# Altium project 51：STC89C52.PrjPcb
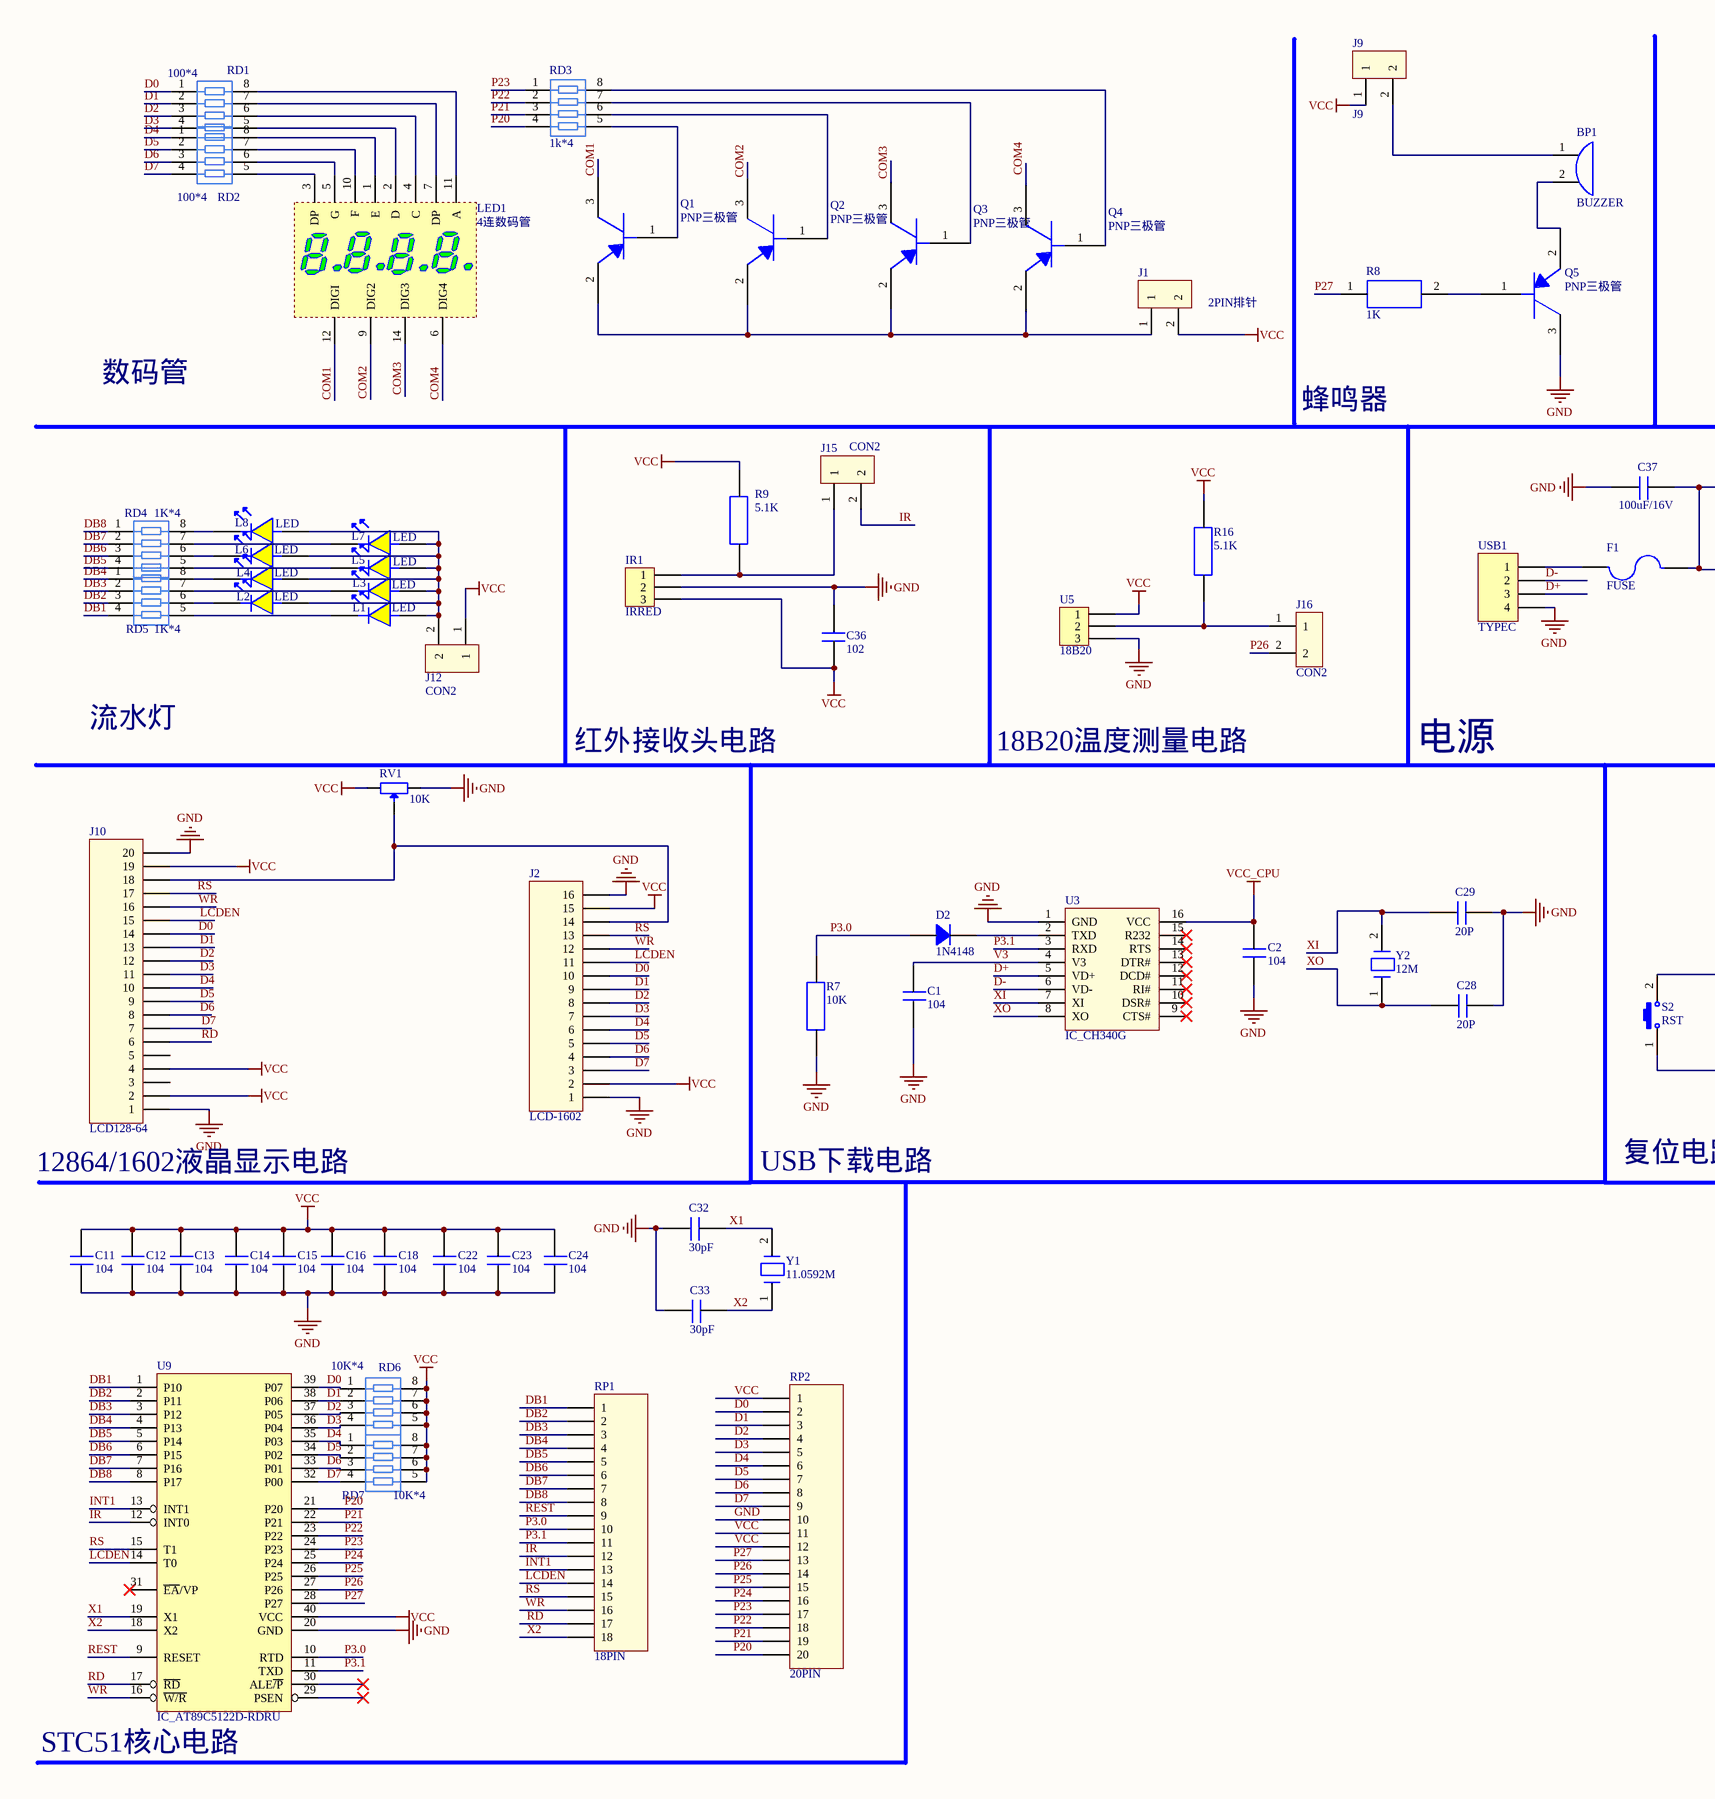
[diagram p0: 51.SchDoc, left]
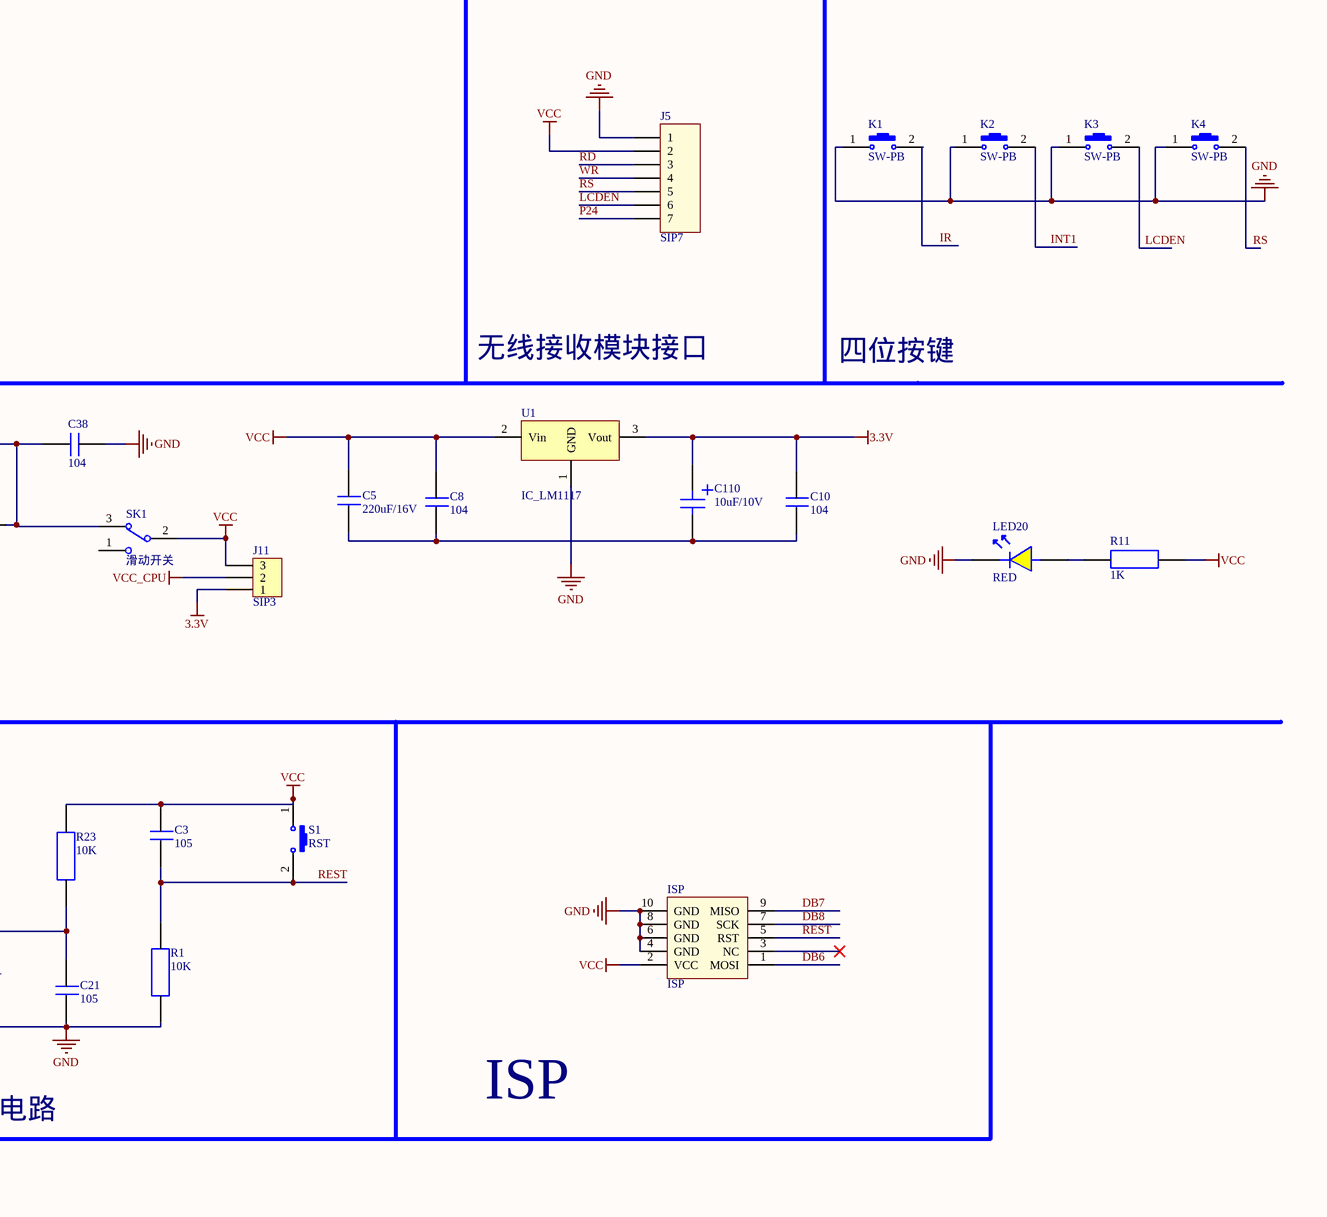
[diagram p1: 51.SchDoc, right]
1 sheet, 85 parts. Net scope: global (net labels, ports and power ports of the same name join across sheets).
Board file: 51.PcbDoc

## Sheet 51.SchDoc
size A2; SheetNumber: 1; SheetTotal: 1

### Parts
BP1  BUZZER  [BUZZER]
C1  104  [FPC-0402C]
C2  104  [FPC-0402C]
C3  105  [FPC-0402C]
C5  220uF/16V  [FPC-0402C]
C8  104  [FPC-0402C]
C10  104  [FPC-0402C]
C11  104  [FPC-0402C]
C12  104  [FPC-0402C]
C13  104  [FPC-0402C]
C14  104  [FPC-0402C]
C15  104  [FPC-0402C]
C16  104  [FPC-0402C]
C18  104  [FPC-0402C]
C21  105  [FPC-0402C]
C22  104  [FPC-0402C]
C23  104  [FPC-0402C]
C24  104  [FPC-0402C]
C28  20P  [FPC-0402C]
C29  20P  [FPC-0402C]
C32  30pF  [FPC-0402C]
C33  30pF  [FPC-0402C]
C36  102  [FPC-0402C]
C37  100uF/16V  [FPC-CPCSM-3R2X8R0-1]
C38  104  [FPC-0402C]
C110  10uF/10V  [FPC-0402C]
D2  1N4148  [FPC-1206D]
F1  FUSE  [1206F]
IR1  IRRED  [HDR1X3]
ISP  ISP  [IDE-10]
J1  2PIN排针  [HDR1X2]
J2  LCD-1602  [HDR1X16]
J5  SIP7  [HDR1X7]
J9  J9  [HDR1X2]
J10  LCD128-64  [HDR1X20]
J11  SIP3  [HDR1X3]
J12  CON2  [HDR1X2]
J15  CON2  [HDR1X2]
J16  CON2  [HDR1X2]
K1  SW-PB  [SW-PB]
K2  SW-PB  [SW-PB]
K3  SW-PB  [SW-PB]
K4  SW-PB  [SW-PB]
L1  LED  [FPC-0805D]
L2  LED  [FPC-0805D]
L3  LED  [FPC-0805D]
L4  LED  [FPC-0805D]
L5  LED  [FPC-0805D]
L6  LED  [FPC-0805D]
L7  LED  [FPC-0805D]
L8  LED  [FPC-0805D]
LED1  4连数码管  [CL3641A]
LED20  RED  [FPC-0805D]
Q1  PNP三极管  [FPC-SOT323]
Q2  PNP三极管  [FPC-SOT323]
Q3  PNP三极管  [FPC-SOT323]
Q4  PNP三极管  [FPC-SOT323]
Q5  PNP三极管  [FPC-SOT323]
R1  10K  [FPC-0402R]
R7  10K  [FPC-0402R]
R8  1K  [FPC-0402R]
R9  5.1K  [FPC-0402R]
R11  1K  [FPC-0402R]
R16  5.1K  [FPC-0402R]
R23  10K  [FPC-0402R]
RD1  100*4  [FPC-0603RA]
RD2  100*4  [FPC-0603RA]
RD3  1k*4  [FPC-0603RA]
RD4  1K*4  [FPC-0603RA]
RD5  1K*4  [FPC-0603RA]
RD6  10K*4  [FPC-0603RA]
RD7  10K*4  [FPC-0603RA]
RP1  18PIN  [HDR1X18]
RP2  20PIN  [HDR1X20]
RV1  10K  [RV]
S1  RST  [SW-PB]
S2  RST  [SW-PB]
SK1  滑动开关  [SS-12F44]
U1  IC_LM1117  [SOP-223-3L]
U3  IC_CH340G  [FPC-SO16-150]
U5  18B20  [HDR1X3]
U9  IC_AT89C5122D-RDRU  [DIP40]
USB1  TYPEC  [USB_A]
Y1  11.0592M  [FPC-CO2-5R0X11R5-V]
Y2  12M  [FPC-CO2-5R0X11R5-V]

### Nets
3.3V: C10.2 C110.1 J11.1 U1.3(Vout)
GND: C1.1 C2.1 C11.1 C12.1 C13.1 C14.1 C15.1 C16.1 C18.1 C21.1 C22.1 C23.1 C24.1 C28.2 C29.2 C32.1 C33.1 C36.1 C37.1 C38.2 IR1.2 ISP.4(GND) ISP.6(GND) ISP.8(GND) ISP.10(GND) J2.1 J2.16 J5.1 J10.1 J10.20 K1.1 K2.1 K3.1 K4.1 LED20.1 Q5.3 R1.1 R7.1 RP2.10 RV1.2 S2.1 U1.1(GND) U3.1(GND) U5.3 U9.20(GND) USB1.4
VCC: C3.2 C5.2 C8.2 C11.2 C12.2 C13.2 C14.2 C15.2 C16.2 C18.2 C22.2 C23.2 C24.2 C36.2 IR1.3 ISP.2(VCC) J1.2 J2.2 J2.15 J5.2 J9.1 J10.2 J10.4 J10.19 J11.3 J12.1 R9.2 R11.2 R16.2 R23.2 RD6.5 RD6.6 RD6.7 RD6.8 RD7.5 RD7.6 RD7.7 RD7.8 RP2.1 RP2.11 RP2.12 RV1.1 S1.1 SK1.2 U1.2(Vin) U5.1 U9.40(VCC)
VCC_CPU: C2.2 J11.2 U3.16(VCC)
COM1: LED1.12(DIGI) Q1.3
COM2: LED1.9(DIG2) Q2.3
COM3: LED1.14(DIG3) Q3.3
COM4: LED1.6(DIG4) Q4.3
D0: J2.10 J10.14 RD1.1 RD6.1 RP2.2 U9.39(P07)
D1: J2.9 J10.13 RD1.2 RD6.2 RP2.3 U9.38(P06)
D2: J2.8 J10.12 RD1.3 RD6.3 RP2.4 U9.37(P05)
D3: J2.7 J10.11 RD1.4 RD6.4 RP2.5 U9.36(P04)
D4: J2.6 J10.10 RD2.1 RD7.1 RP2.6 U9.35(P03)
D5: J2.5 J10.9 RD2.2 RD7.2 RP2.7 U9.34(P02)
D6: J2.4 J10.8 RD2.3 RD7.3 RP2.8 U9.33(P01)
D7: J2.3 J10.7 RD2.4 RD7.4 RP2.9 U9.32(P00)
D+: U3.5(VD+) USB1.3
D-: U3.6(VD-) USB1.2
DB1: RD5.4 RP1.1 U9.1(P10)
DB2: RD5.3 RP1.2 U9.2(P11)
DB3: RD5.2 RP1.3 U9.3(P12)
DB4: RD5.1 RP1.4 U9.4(P13)
DB5: RD4.4 RP1.5 U9.5(P14)
DB6: ISP.1(MOSI) RD4.3 RP1.6 U9.6(P15)
DB7: ISP.9(MISO) RD4.2 RP1.7 U9.7(P16)
DB8: ISP.7(SCK) RD4.1 RP1.8 U9.8(P17)
INT1: K2.2 RP1.13 U9.13(INT1)
IR: J15.2 K1.2 RP1.12 U9.12(INT0)
LCDEN: J2.11 J5.6 J10.15 K3.2 RP1.14 U9.14(T0)
P3.0: D2.1 R7.2 RP1.10 U9.10(RTD)
P3.1: RP1.11 U3.3(RXD) U9.11(TXD)
P20: RD3.4 RP2.20 U9.21(P20)
P21: RD3.3 RP2.19 U9.22(P21)
P22: RD3.2 RP2.18 U9.23(P22)
P23: RD3.1 RP2.17 U9.24(P23)
P24: J5.7 RP2.16 U9.25(P24)
P25: RP2.15 U9.26(P25)
P26: J16.2 RP2.14 U9.27(P26)
P27: R8.1 RP2.13 U9.28(P27)
RD: J5.3 J10.6 RP1.17 U9.17(~{RD})
REST: C3.1 ISP.5(RST) R1.2 RP1.9 S1.2 U9.9(RESET)
RS: J2.13 J5.5 J10.17 K4.2 RP1.15 U9.15(T1)
V3: C1.2 U3.4(V3)
WR: J2.12 J5.4 J10.16 RP1.16 U9.16(~{W}~{/R})
X1: C32.2 U9.19(X1) Y1.2
X2: C33.2 RP1.18 U9.18(X2) Y1.1
XI: C29.1 U3.7(XI) Y2.2
XO: C28.1 U3.8(XO) Y2.1
NetBP1_1: BP1.1 J9.2
NetBP1_2: BP1.2 Q5.2
NetC5_1: C5.1 C8.1 C10.1 C110.2
NetC21_2: C21.2 R23.1 S2.2
NetC37_2: C37.2 C38.1 F1.1 SK1.3
NetD2_2: D2.2 U3.2(TXD)
NetF1_2: F1.2 USB1.1
NetIR1_1: IR1.1 J15.1 R9.1
NetJ1_1: J1.1 Q1.2 Q2.2 Q3.2 Q4.2
NetJ2_14: J2.14 J10.18 RV1.3
NetJ12_2: J12.2 L1.2 L2.2 L3.2 L4.2 L5.2 L6.2 L7.2 L8.2
NetJ16_1: J16.1 R16.1 U5.2
NetL1_1: L1.1 RD5.5
NetL2_1: L2.1 RD5.6
NetL3_1: L3.1 RD5.7
NetL4_1: L4.1 RD5.8
NetL5_1: L5.1 RD4.5
NetL6_1: L6.1 RD4.6
NetL7_1: L7.1 RD4.7
NetL8_1: L8.1 RD4.8
NetLED1_1: LED1.1(E) RD2.8
NetLED1_2: LED1.2(D) RD1.5
NetLED1_3: LED1.3(DP) RD2.5
NetLED1_4: LED1.4(C) RD1.6
NetLED1_5: LED1.5(G) RD2.6
NetLED1_7: LED1.7(DP) RD1.7
NetLED1_10: LED1.10(F) RD2.7
NetLED1_11: LED1.11(A) RD1.8
NetLED20_2: LED20.2 R11.1
NetQ1_1: Q1.1 RD3.5
NetQ2_1: Q2.1 RD3.6
NetQ3_1: Q3.1 RD3.7
NetQ4_1: Q4.1 RD3.8
NetQ5_1: Q5.1 R8.2

Not connected (* = marked no-connect by the designer): ISP 3(NC)*; J10 3 5; SK1 1; U3 9(CTS#)* 10(DSR#)* 11(RI#)* 12(DCD#)* 13(DTR#)* 14(RTS)* 15(R232)*; U9 29(PSEN)* 30(ALE~{/P})* 31(~{EA}/VP)*

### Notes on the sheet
- 数码管
- 蜂鸣器
- 无线接收模块接口
- 四位按键
- 流水灯
- 红外接收头电路
- 18B20温度测量电路
- 电源
- (near J10) 12864/1602液晶显示电路
- USB下载电路
- 复位电路
- ISP
- (near U9) STC51核心电路

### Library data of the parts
C1-C3 C5 C8 C10-C16 C18 C21-C24 C28 C29 C32 C33 C36-C38 = CAP
C110 = CAP1
D2 = 二极管
IR1 U5 = SIP3
ISP = IC_ISP
J2 = 16PIN
J9 J12 J15 J16 = 2PIN排针
J10 = 20PIN
K1-K4 S1 S2 = KEY
LED20 = LED
R1 R7-R9 R11 R16 R23 = res1
RD1-RD7 = RP
RV1 = VR
USB1 = USB座
Y1 Y2 = XT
